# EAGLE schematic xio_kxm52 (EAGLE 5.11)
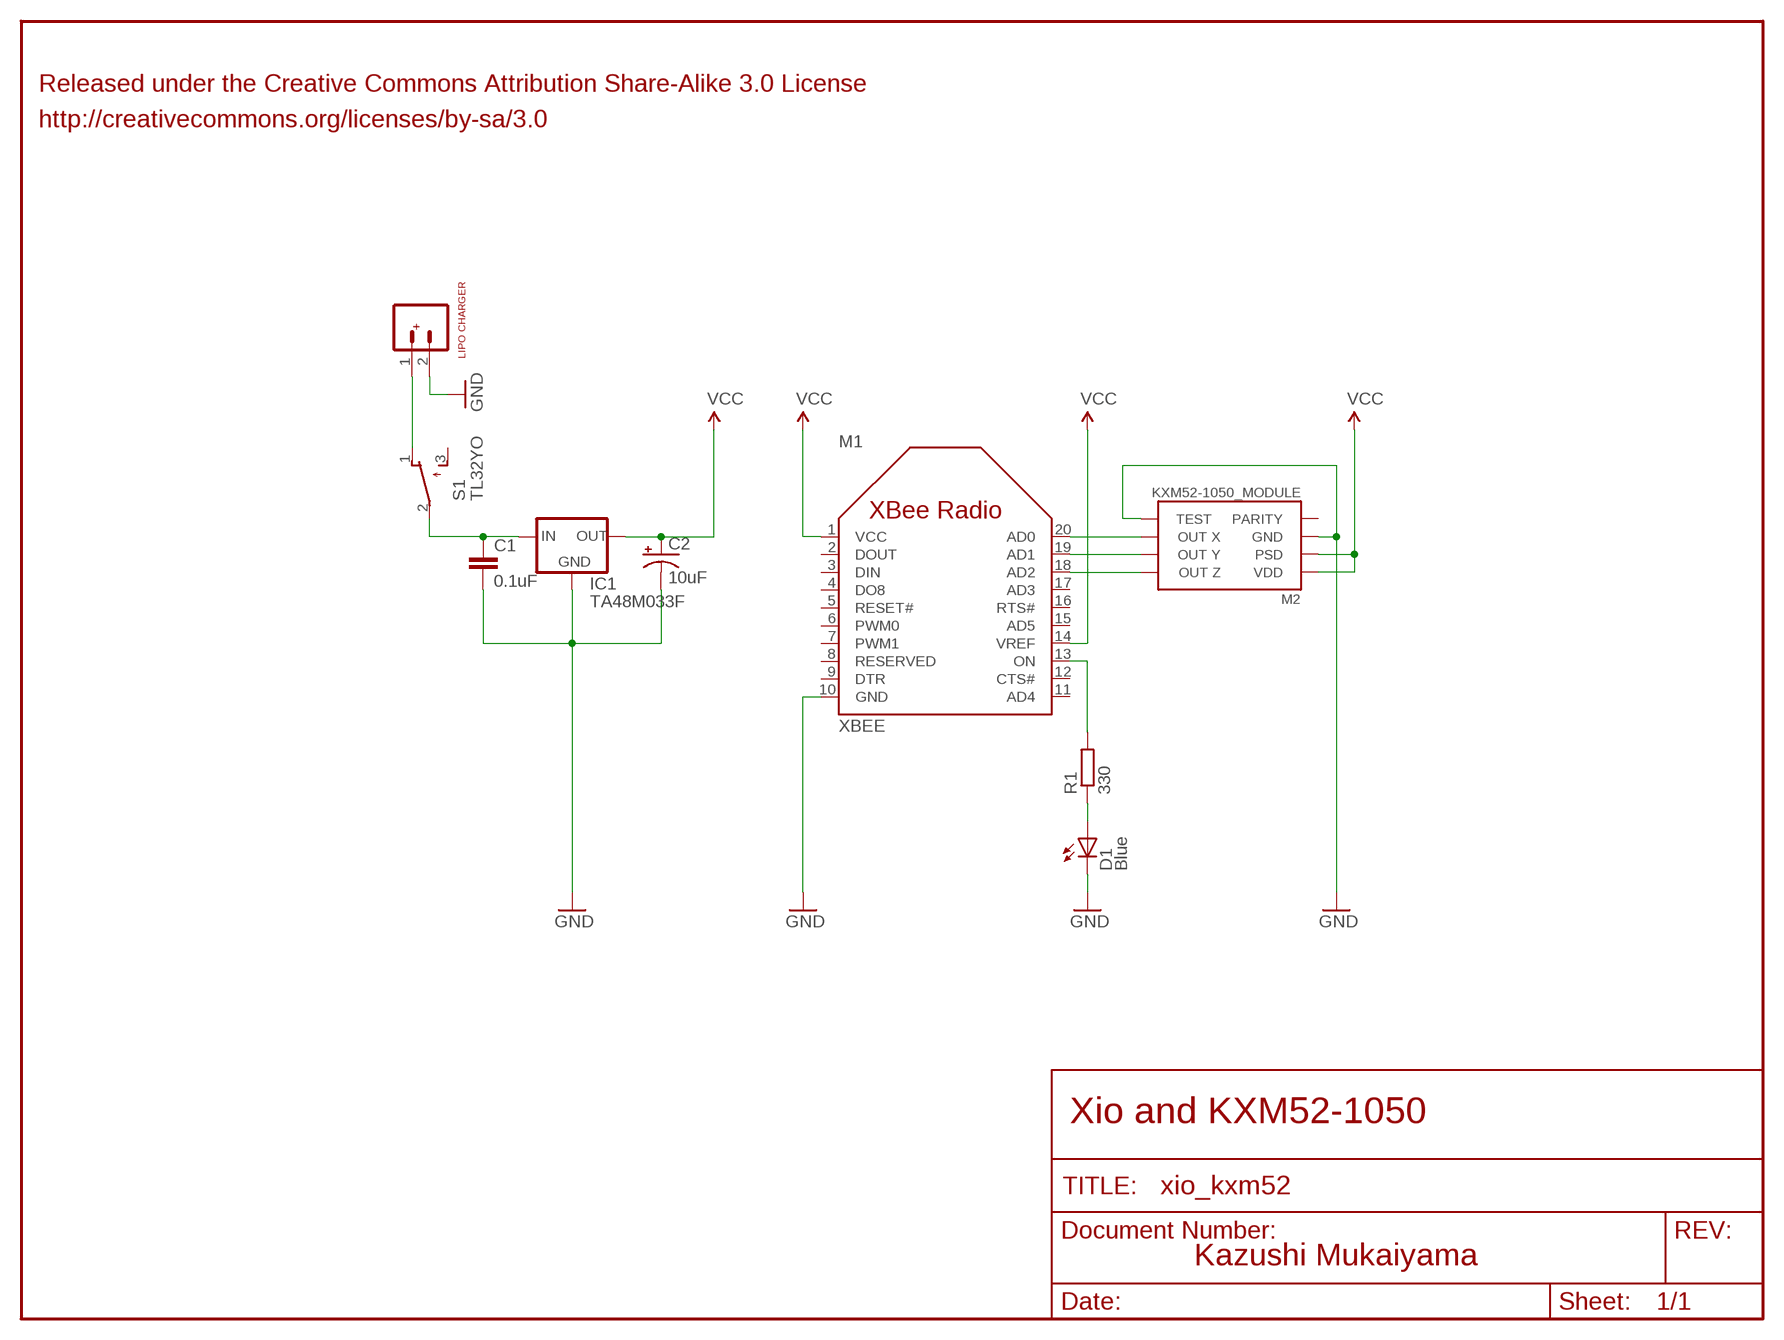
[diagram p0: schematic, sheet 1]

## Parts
C1  0.1uF  CAPPTH  [CAP-PTH-SMALL]
C2  10uF  CAP_POLPTH2  [CPOL-RADIAL-10UF-25V]
D1  Blue  LED3MM  [LED3MM]
IC1  TA48M033F  V_REG_78XX-HSIP3  [HSIP3]
JP1  SPARKFUN_LIPO_CHARGERPTH  [BASIC_MINIUSB_PAC]
M1  XBEE  [XBEE]
M2  KXM52-1050_MODULE  [KXM52-1050_MODULE]
R1  330  R-EU_0204/7  [0204/7]
S1  TL32YO  [TL3XYO]

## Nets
GND: C1.2 C2.2(-) D1.K(C) IC1.GND JP1.2 M1.10(GND) M2.P$3(GND) M2.P$5(SELF_TEST)
N$1: M1.13(ON) R1.2
N$2: M1.20(AD0) M2.P$6(OUT_X)
N$3: M1.19(AD1) M2.P$7(OUT_Y)
N$4: C1.1 IC1.IN S1.2(P)
N$5: M1.18(AD2) M2.P$8(OUT_Z)
N$6: D1.A R1.1
N$7: JP1.1 S1.1(O)
VCC [VCC]: C2.1(+) IC1.OUT M1.1(VCC) M1.14(VREF) M2.P$1(VDD) M2.P$2(PSD)
Unconnected: M1.2(DOUT) M1.3(DIN) M1.4(DO8) M1.5(RESET#) M1.6(PWM0) M1.7(PWM1) M1.8(RESERVED) M1.9(DTR) M1.11(AD4) M1.12(CTS#) M1.15(AD5) M1.16(RTS#) M1.17(AD3) M2.P$4(PARITY) S1.3(S)

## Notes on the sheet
- Released under the Creative Commons Attribution Share-Alike 3.0 License
- http://creativecommons.org/licenses/by-sa/3.0
- Xio and KXM52-1050
- Kazushi Mukaiyama

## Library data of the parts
C1 = SparkFun:CAP: Capacitor
C2 = SparkFun:CAP_POL: Capacitor Polarized
D1 = led:LED: LED
IC1 = SparkFun:V_REG_78XX: Voltage Regulator Standard 7805 5V regulator. IGO (Input Ground Output). Spark Fun Electronics SKU : COM-00107
JP1 = kazushi:SPARKFUN_LIPO_CHARGER: Header 2
M1 = digi_xbee:XBEE
M2 = akizuki_KXM52-1050:KXM52-1050_MODULE
R1 = rcl:R-EU_: RESISTOR, European symbol
S1 = switch:TL32YO: TINY SWITCH ON - MOM Source: http://www2.produktinfo.conrad.com/datenblaetter/700000-724999/705152-da-01-de-Subminiaturschalter_TL_36YO.pdf

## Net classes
0 Default: width 0.203 mm
1 VCC: width 0.381 mm
2 LEDPower: width 0.203 mm
3 ButtonSignal: width 0.203 mm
